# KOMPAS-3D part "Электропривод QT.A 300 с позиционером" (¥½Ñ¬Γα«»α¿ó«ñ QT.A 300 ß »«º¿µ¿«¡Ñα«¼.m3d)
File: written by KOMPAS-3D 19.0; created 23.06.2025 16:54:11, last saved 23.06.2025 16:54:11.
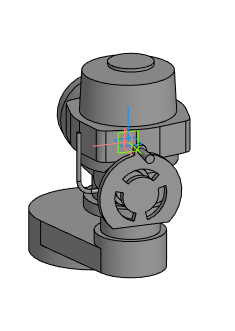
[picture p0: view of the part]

Document properties: Автор: Евгений; Полное имя файла: E:\Dendor Работа Сачек\3D для проектировщиков\3.5 Тип QT.А Электропривод\stp_Электропривод QT.A с позиционером\Электропривод QT.A 300 с позиционером.m3d

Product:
- Part/product: Электропривод QT.A 300 с позиционером

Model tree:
1. Операция без истории:1  (labels: Электропривод QT.A 300 с позиционером)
